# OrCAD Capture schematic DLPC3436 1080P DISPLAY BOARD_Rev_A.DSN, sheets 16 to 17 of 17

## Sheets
16 P07: FPGA - DAC Interface: size D
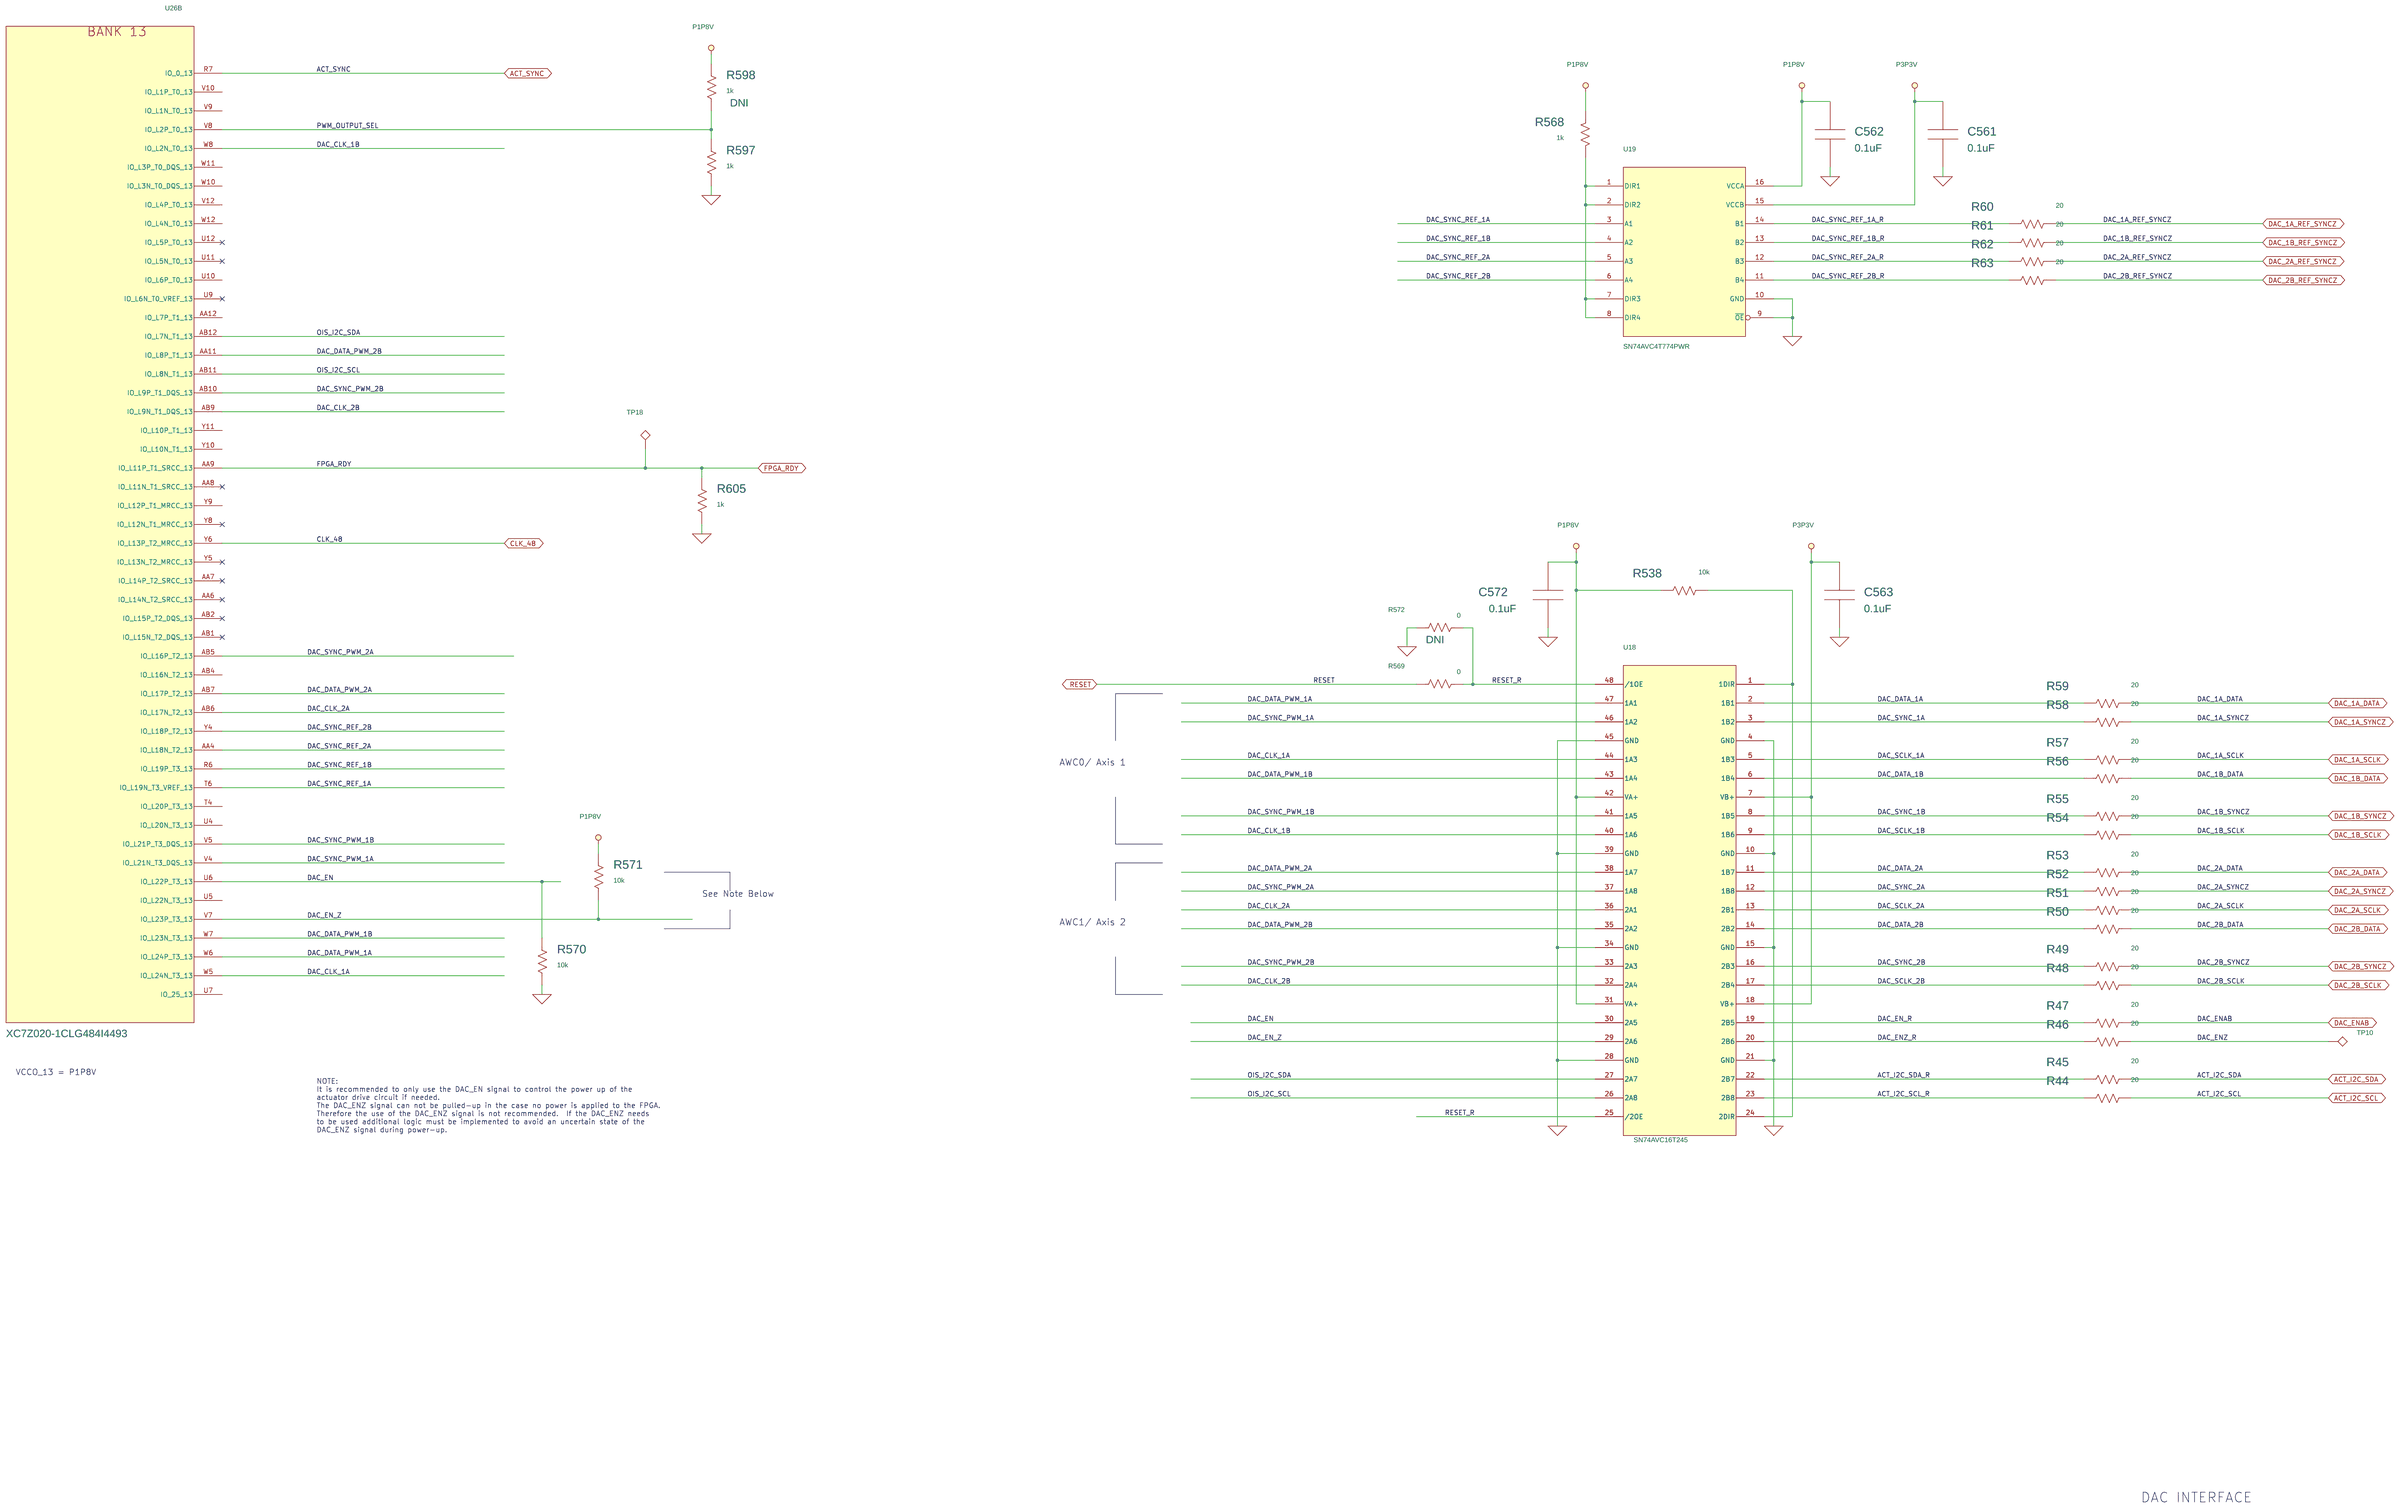
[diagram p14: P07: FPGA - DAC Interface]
17 P02: FPGA Boot, Flash, Reset: size D
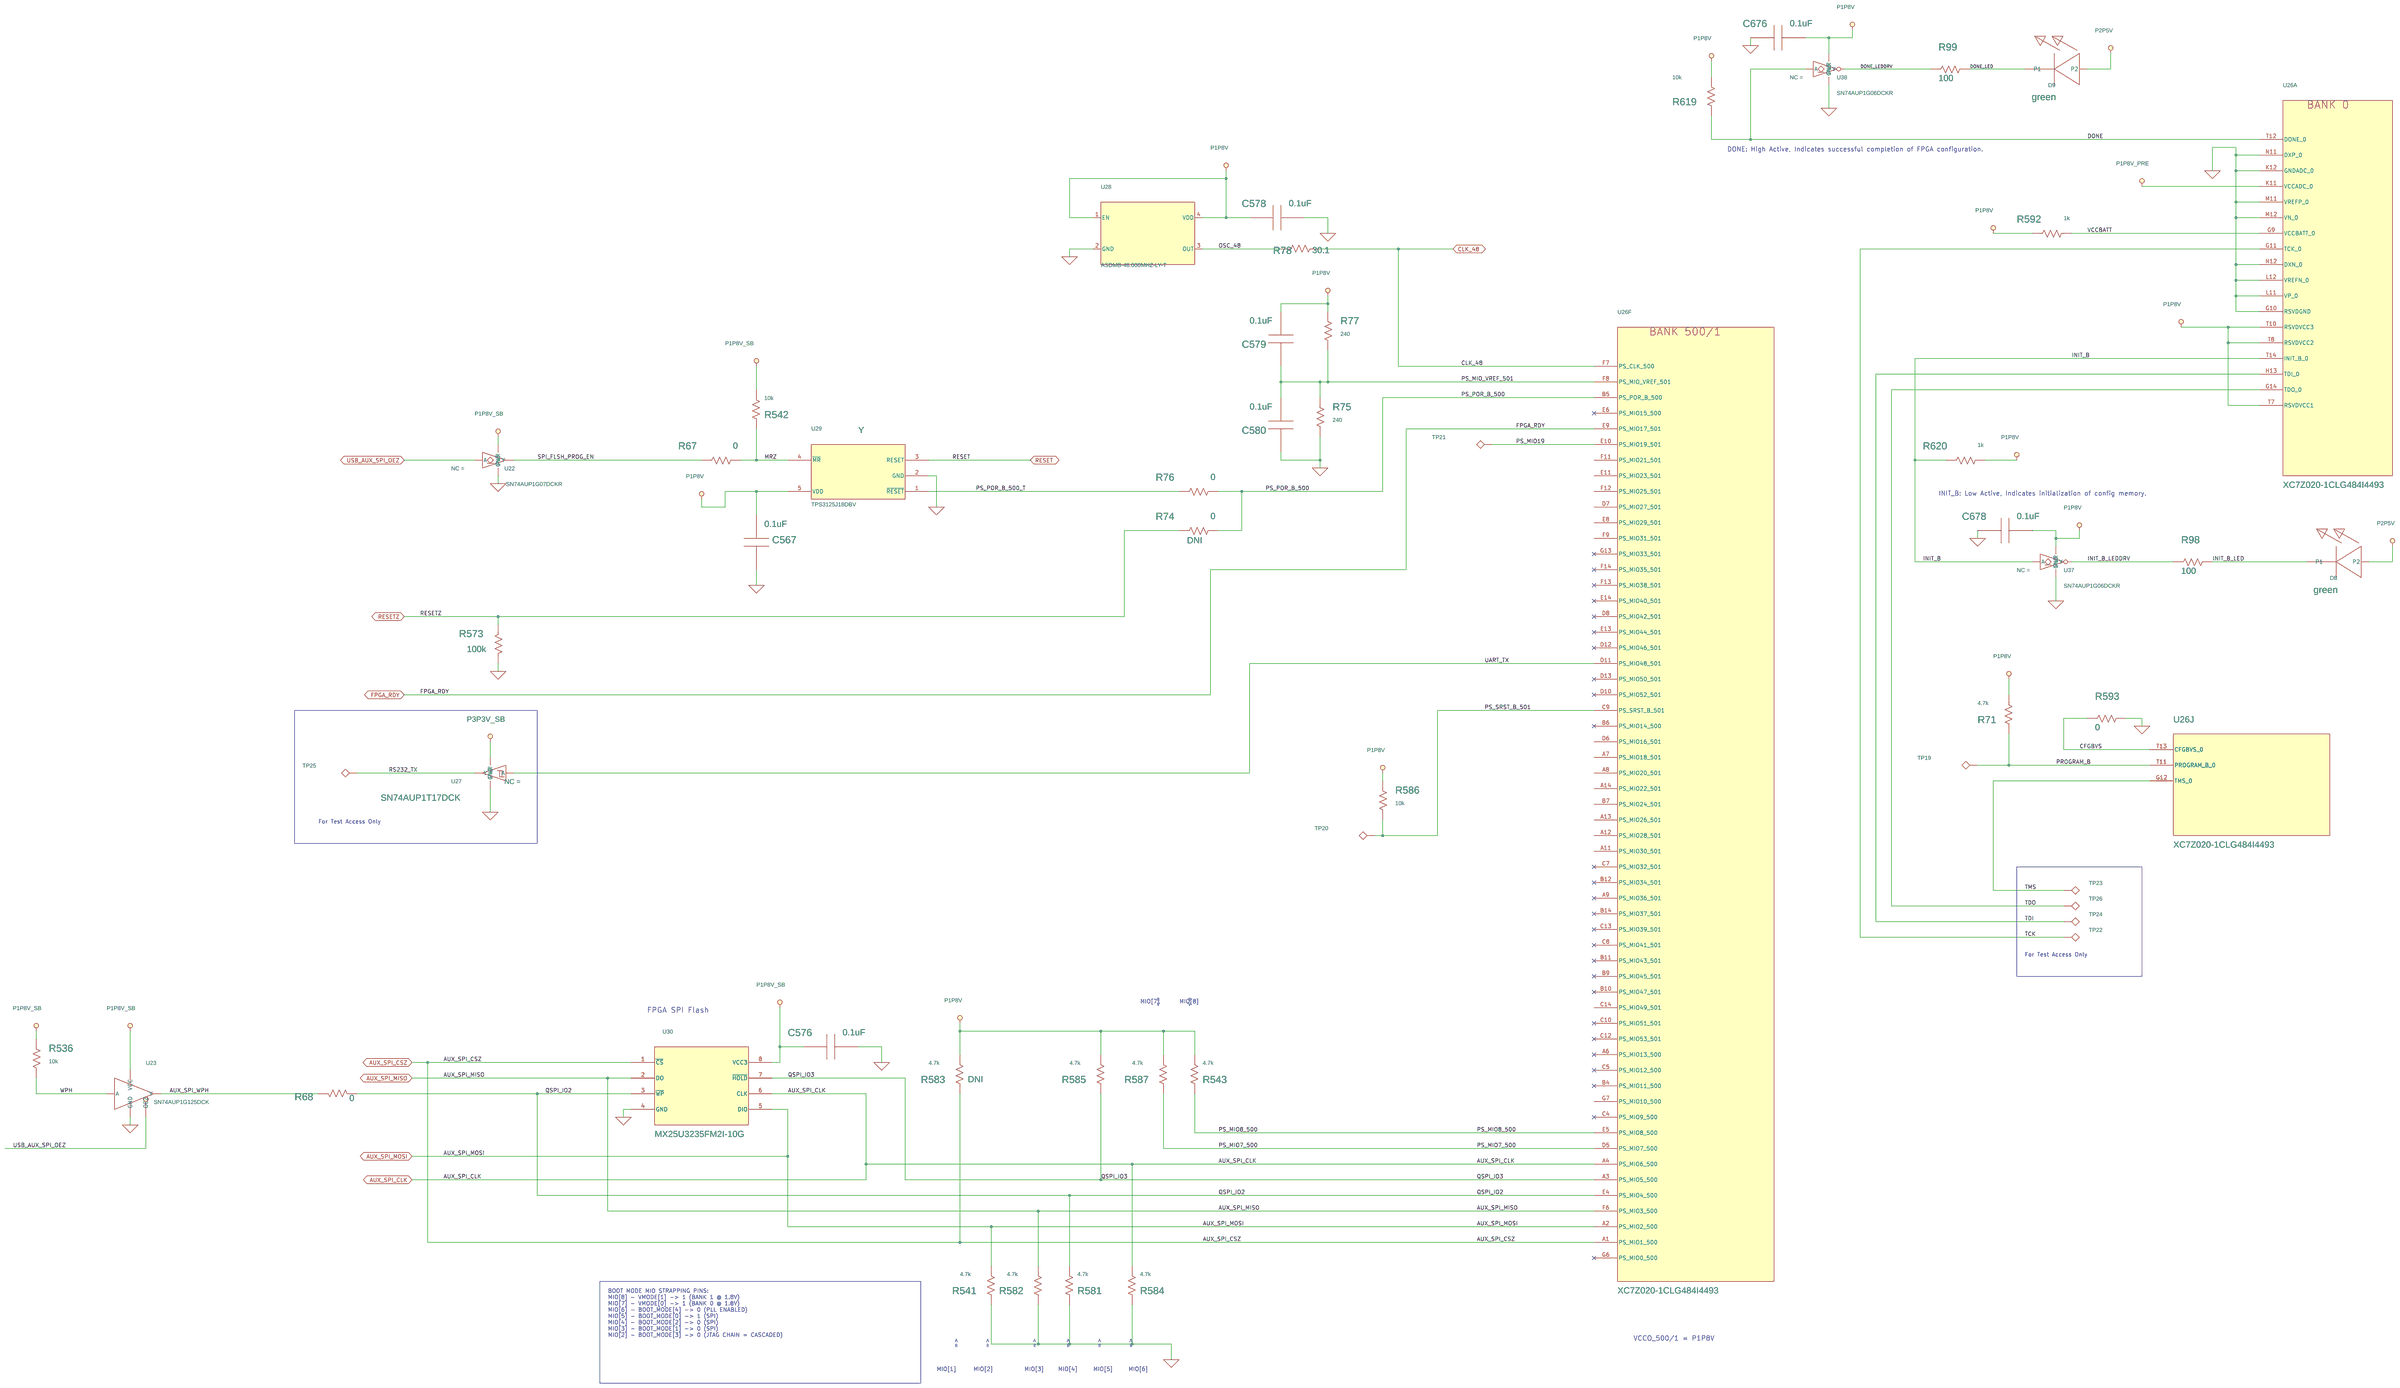
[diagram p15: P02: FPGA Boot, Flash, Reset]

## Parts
sheet P02: FPGA Boot, Flash, Reset
C567  0.1uF  [0402_AVXA]
C576  0.1uF  [0402_AVXA]
C578  0.1uF  [0402_AVXA]
C579  0.1uF  [0402_AVXA]
C580  0.1uF  [0402_AVXA]
C676  0.1uF  [0402_AVXA]
C678  0.1uF  [0402_AVXA]
D8  green  [1206]
D9  green  [1206]
R67  0  [0402]
R68  0  [0402]
R71  4.7k  [0402]
R74  0  [0402]
R75  240  [0402]
R76  0  [0402]
R77  240  [0402]
R78  30.1  [0402]
R98  100  [0402]
R99  100  [0402]
R536  10k  [0402]
R541  4.7k  [0402]
R542  10k  [0402]
R543  4.7k  [0402]
R573  100k  [0402]
R581  4.7k  [0402]
R582  4.7k  [0402]
R583  4.7k  [0402]
R584  4.7k  [0402]
R585  4.7k  [0402]
R586  10k  [0402]
R587  4.7k  [0402]
R592  1k  [0402]
R593  0  [0402]
R619  10k  [0402]
R620  1k  [0402]
TP19  TP,12mil Drill,32mil Pad  [HOLE_PLATED_12mil_DRILL_32mil_PAD]
TP20  TP,12mil Drill,32mil Pad  [HOLE_PLATED_12mil_DRILL_32mil_PAD]
TP21  TP,12mil Drill,32mil Pad  [HOLE_PLATED_12mil_DRILL_32mil_PAD]
TP22  TP40  [TP40]
TP23  TP40  [TP40]
TP24  TP40  [TP40]
TP25  TP40  [TP40]
TP26  TP40  [TP40]
U22  SN74AUP1G07DCK  [U_5_DCK]
U23  SN74AUP1G125DCK  [U_5_DCK]
U27  SN74AUP1T17DCK  [U_5_DCK]
U28  48MHz  [ECS-2018_2p5mmx2mm]
U29  TPS3125J18DBV  [DBV_R-PDS0-G5]
U30  MX25U3235FM2I-10G  [SOIC-8_208mil]
U37  SN74AUP1G06DCK  [U_5_DCK]
U38  SN74AUP1G06DCK  [U_5_DCK]
sheet P03: Parallel Video Input
U26  XC7Z020-1CLG484I4493  [Xilinx_CLG484]  (sections A,B,C,D,E,F,G,H,I,J)
sheet P07: FPGA - DAC Interface
C561  0.1uF  [0402_AVXA]
C562  0.1uF  [0402_AVXA]
C563  0.1uF  [0402_AVXA]
C572  0.1uF  [0402_AVXA]
R44  20  [0201_R]
R45  20  [0201_R]
R46  20  [0201_R]
R47  20  [0201_R]
R48  20  [0201_R]
R49  20  [0201_R]
R50  20  [0201_R]
R51  20  [0201_R]
R52  20  [0201_R]
R53  20  [0201_R]
R54  20  [0201_R]
R55  20  [0201_R]
R56  20  [0201_R]
R57  20  [0201_R]
R58  20  [0201_R]
R59  20  [0201_R]
R60  20  [0201_R]
R61  20  [0201_R]
R62  20  [0201_R]
R63  20  [0201_R]
R538  10k  [0402]
R568  1k  [0402]
R569  0  [0402]
R570  10k  [0402]
R571  10k  [0402]
R572  0  [0402]
R597  1k  [0402]
R598  1k  [0402]
R605  1k  [0402]
TP10  TP,12mil Drill,32mil Pad  [HOLE_PLATED_12mil_DRILL_32mil_PAD]
TP18  TP40  [TP40]
U18  SN74AVC16T245  [SOIC48-DGG_TI]
U19  SN74AVC4T774PWR  [TSSOP16_PW]

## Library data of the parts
C567 = PAS,CAP,NP,large: DigiKey: 445-4952-1-ND; DigiReel: 445-4952-6-ND; Family: passive; Index PN: 681; Install: Y; Lead Style: SMT; MFG: TDK; Material: x7r; P/D_NUM: C1005X7R1C104K050BC; Part Number: C1005X7R1C104K050BC; Part Specific: CAP CER .1UF 16V X7R 0402; TOLERANCE: 10%; Type: capacitor; VENDOR: TDK; VPC: 16V
C561-C563 C572 C576 C578-C580 C676 C678 = PAS,CAP,NP,large: DigiKey: 445-4952-1-ND; DigiReel: 445-4952-6-ND; Family: passive; Index PN: 681; Lead Style: SMT; MFG: TDK; Material: x7r; P/D_NUM: C1005X7R1C104K050BC; Part Number: C1005X7R1C104K050BC; Part Specific: CAP CER .1UF 16V X7R 0402; TOLERANCE: 10%; Type: capacitor; VENDOR: TDK; VPC: 16V
D8 D9 = PAS,DIODE,LED,large: DigiKey: 67-1357-1-ND; DigiReel: 67-1357-6-ND; Family: passive; Index PN: 31; Install: Y; Lead Style: SMT; MFG: Lumex; P/D_NUM: SML-LX1206GC-TR; Part Number: SML-LX1206GC-TR; Part Specific: LED 565NM WTR CLR GREEN 1206 SMD; Type: diode,led; VENDOR: Lumex
R67 R68 R76 = PAS,R,large: DigiKey: P0.0JCT-ND; DigiReel: P0.0JDKR-ND; Family: passive; Index PN: 687; Install: Y; Lead Style: SMT; MFG: Panasonic; Material: chip; P/D_NUM: ERJ-2GE0R00X; Part Number: ERJ-2GE0R00X; Part Specific: RES 0.0 OHM 1/16W 0402 SMD; Power: 1/16W; Type: resistor; VPC: 1/16W; Vendor: Panasonic
R71 R543 R581 R582 R584 R587 = PAS,R,large: DigiKey: P4.70KLCT-ND; DigiReel: P4.70KLDKR-ND; Family: passive; Index PN: 1219; Lead Style: SMT; MFG: Panasonic; P/D_NUM: ERJ-2RKF4701X; Part Number: ERJ-2RKF4701X; Part Specific: RES 4.7K OHM 1/10W 1% 0402 SMD; Type: resistor; VENDOR: Panasonic; VPC: 1/16W
R74 R572 = PAS,R,large: DigiKey: P0.0JCT-ND; DigiReel: P0.0JDKR-ND; Family: passive; Index PN: 687; Install: DNI; Lead Style: SMT; MFG: Panasonic; Material: chip; P/D_NUM: ERJ-2GE0R00X; Part Number: ERJ-2GE0R00X; Part Specific: RES 0.0 OHM 1/16W 0402 SMD; Power: 1/16W; Type: resistor; VPC: 1/16W; Vendor: Panasonic
R75 R77 = PAS,R,large: DigiKey: P240LCT-ND; DigiReel: P240LDKR-ND; Family: passive; Index PN: 1303; Lead Style: SMT; MFG: Panasonic; P/D_NUM: ERJ-2RKF2400X; Part Number: ERJ-2RKF2400X; Part Specific: RES SMD 240 OHM 1% 1/10W 0402; Type: resistor; VENDOR: Panasonic; VPC: 1/16W
R78 = PAS,R,large: DigiKey: P30.1LCT-ND; DigiReel: P30.1LDKR-ND; Family: passive; Index PN: 976; Lead Style: SMT; MFG: Panasonic; Material: chip; P/D_NUM: ERJ-2RKF30R1X; Part Number: ERJ-2RKF30R1X; Part Specific: RES 30.1 OHM 1/16W 1% 0402 SMD; Power: 1/16W; TOLERANCE: 1%; Type: resistor; VENDOR: Panasonic; VPC: 1/16W
R98 R99 = PAS,R,large: DigiKey: P100LCT-ND; DigiReel: P100LDKR-ND; Family: passive; Index PN: 690; Lead Style: SMT; MFG: Panasonic; Material: chip; P/D_NUM: ERJ-2RKF1000X; Part Number: ERJ-2RKF1000X; Part Specific: RES 100 OHM 1/10W 1% 0402 SMD; Power: 1/16W; TOLERANCE: 1%; Type: resistor; VENDOR: Panasonic; VPC: 1/16W
R536 R542 R586 R619 = PAS,R,large: DigiKey: P10.0KLCT-ND; DigiReel: P10.0KLDKR-ND; Family: passive; Index PN: 680; Install: Y; Lead Style: SMT; MFG: Panasonic; Material: chip; P/D_NUM: ERJ-2RKF1002X; Part Number: ERJ-2RKF1002X; Part Specific: RES SMD 10K OHM 1% 1/10W 0402; Power: 1/16W; TOLERANCE: 1%; Type: resistor; VENDOR: Panasonic; VPC: 1/16W
R541 R585 = PAS,R,large: DigiKey: P4.70KLCT-ND; DigiReel: P4.70KLDKR-ND; Family: passive; Index PN: 1219; Install: Y; Lead Style: SMT; MFG: Panasonic; P/D_NUM: ERJ-2RKF4701X; Part Number: ERJ-2RKF4701X; Part Specific: RES 4.7K OHM 1/10W 1% 0402 SMD; Type: resistor; VENDOR: Panasonic; VPC: 1/16W
R573 = PAS,R,large: DigiKey: 541-100KLCT-ND; DigiReel: 541-100KLDKR-ND; Family: passive; Index PN: 712; Lead Style: SMT; MFG: Vishay/Dale; Material: chip; P/D_NUM: CRCW0402100KFKED; Part Number: CRCW0402100KFKED; Part Specific: RES 100K OHM 1/10W 1% 0402 SMD; Power: 1/16W; TOLERANCE: 1%; Type: resistor; VPC: 1/16W; Vendor: Vishay/Dale
R583 = PAS,R,large: DigiKey: P4.70KLCT-ND; DigiReel: P4.70KLDKR-ND; Family: passive; Index PN: 1219; Install: DNI; Lead Style: SMT; MFG: Panasonic; P/D_NUM: ERJ-2RKF4701X; Part Number: ERJ-2RKF4701X; Part Specific: RES 4.7K OHM 1/10W 1% 0402 SMD; Type: resistor; VENDOR: Panasonic; VPC: 1/16W
R568 R592 R597 R605 R620 = PAS,R,large: DigiKey: P1.00KLCT-ND; DigiReel: P1.00KLDKR-ND; Family: passive; Index PN: 684; Install: Y; Lead Style: SMT; MFG: Panasonic; Material: chip; P/D_NUM: ERJ-2RKF1001X; Part Number: ERJ-2RKF1001X; Part Specific: RES 1.00K OHM 1/10W 1% 0402 SMD; Power: 1/16W; TOLERANCE: 1%; Type: resistor; VENDOR: Panasonic; VPC: 1/16W
R593 = PAS,R,large: DigiKey: P0.0JCT-ND; DigiReel: P0.0JDKR-ND; Family: passive; Index PN: 687; Lead Style: SMT; MFG: Panasonic; Material: chip; P/D_NUM: ERJ-2GE0R00X; Part Number: ERJ-2GE0R00X; Part Specific: RES 0.0 OHM 1/16W 0402 SMD; Power: 1/16W; Type: resistor; VENDOR: Panasonic; VPC: 1/16W
TP10 TP19-TP21 = EM,TERM,TESTPOINT: Family: board feature; Index PN: 122; Install: DNI; MFG: -- NOT A PART --; Type: hole,plated; Vendor: -- NOT A PART --
TP18 TP22-TP26 = EM,TERM,TESTPOINT: DigiKey: ---; DigiReel: ---; Family: board feature; Index PN: 995; Install: DNI; MFG: -- NOT A PART --; Type: hole,plated; Vendor: -- NOT A PART --
U22 = LOG,BUF,OPENDRN,SN74AUP1G07DCK: DigiKey: 296-18256-1-ND; DigiReel: 296-18256-6-ND; Family: logic; Index PN: 1027; Lead Style: SMT; MFG: Texas Instruments; P/D_NUM: SN74AUP1G07DCKR; Part Number: SN74AUP1G07DCKR; Part Specific: IC BUFF/DVR LOW PWR N-INV SC705, open drain; Type: buffer
U23 = LOG,BUF,SN74AUP1G125DCK: DigiKey: 296-21012-1-ND; DigiReel: 296-21012-6-ND; Family: logic; Lead Style: SMT; MFG: Texas Instruments; P/D_NUM: SN74AUP1G125DCKR; Part Number: SN74AUP1G125DCKR; Part Specific: IC BUS BUFFER TRI-ST SC70-5; Pin Cnt: 5; Type: buffer
U27 = LOG,BUF,SCHMITT,SN74AUP1T17DCK: DigiKey: 296-27395-1-ND; DigiReel: 296-27395-6-ND; Family: logic; Index PN: 1199; Lead Style: SMT; MFG: Texas Instruments; P/D_NUM: SN74AUP1T17DCKR; Part Number: SN74AUP1T17DCKR; Part Specific: IC BUFFER SCHMITT TRIG LP SC70-5; Type: buffer
U28 = ANA,OSC,4P,2X: DigiKey: 535-11198-1-ND; DigiReel: 535-11198-6-ND; Family: analog; Index PN: 1346; Install: Y; Lead Style: SMT; MFG: Abracon; P/D_NUM: ASDMB-48.000MHZ-LY-T; Part Number: ASDMB-48.000MHZ-LY-T; Part Specific: OSC MEMS 48.000MHZ CMOS SMD; Type: oscillator; VPC: 1.8V-3.3V; Vendor: Abracon
U29 = PWR,MON,TPS3125: DigiKey: 296-10898-1-ND; DigiReel: 296-10898-6-ND; Family: power; Index PN: 1160; Install: Y; Lead Style: SMT; MFG: Texas Instruments; Part Specific: IC 1.62V SUPPLY MONITOR SOT23-5; Type: monitor; Vendor: Texas Instruments
U30 = MEM,FLASH,SERIAL,W25XxxALxNIG: DigiKey: 1092-1137-ND; DigiReel: ---; Family: memory; Install: Y; Lead Style: SMT; MFG: Macronix; Part Specific: IC FLASH 32M SPI 104MHZ 8SOIC; Type: flash, spi; VENDOR: Macronix; VPC: 1.65-2.0V
U37 U38 = LOG,INV,OPENDRN,SN74AUP1G06DCK: DigiKey: 296-17562-1-ND; DigiReel: 296-17562-6-ND; Family: logic; Index PN: 1026; Lead Style: SMT; MFG: Texas Instruments; P/D_NUM: SN74AUP1G06DCKR; Part Number: SN74AUP1G06DCKR; Part Specific: IC INVERTER SINGLE 1INPUT SC705, open drain; Type: buffer
U26 = TIDLP,XPR_FPGA,Zynq-7020new_0: DigiKey: ---; DigiReel: ---; Family: processor; Index PN: 1304; Lead Style: SMT; MFG: Xilinx; Type: dlp; Vendor: Xilinx
R44-R63 = PAS,R,large: DigiKey: YAG2500CT-ND; DigiReel: YAG2500DKR-ND; Family: passive; Install: Y; Lead Style: SMT; MFG: Yageo; P/D_NUM: RC0201FR-0720RL; Part Number: RC0201FR-0720RL; Part Specific: RES SMD 20 OHM 1% 1/20W 0201; Power: 1%; Type: resistor; VENDOR: Yageo; VPC: 1/20W
R538 R570 R571 = PAS,R,large: DigiKey: P10.0KLCT-ND; DigiReel: P10.0KLDKR-ND; Family: passive; Index PN: 680; Lead Style: SMT; MFG: Panasonic; Material: chip; P/D_NUM: ERJ-2RKF1002X; Part Number: ERJ-2RKF1002X; Part Specific: RES SMD 10K OHM 1% 1/10W 0402; Power: 1/16W; TOLERANCE: 1%; Type: resistor; VENDOR: Panasonic; VPC: 1/16W
R569 = PAS,R,large: DigiKey: P0.0JCT-ND; DigiReel: P0.0JDKR-ND; Family: passive; Index PN: 687; Lead Style: SMT; MFG: Panasonic; Material: chip; P/D_NUM: ERJ-2GE0R00X; Part Number: ERJ-2GE0R00X; Part Specific: RES 0.0 OHM 1/16W 0402 SMD; Power: 1/16W; Type: resistor; VPC: 1/16W; Vendor: Panasonic
R598 = PAS,R,large: DigiKey: P1.00KLCT-ND; DigiReel: P1.00KLDKR-ND; Family: passive; Index PN: 684; Install: DNI; Lead Style: SMT; MFG: Panasonic; Material: chip; P/D_NUM: ERJ-2RKF1001X; Part Number: ERJ-2RKF1001X; Part Specific: RES 1.00K OHM 1/10W 1% 0402 SMD; Power: 1/16W; TOLERANCE: 1%; Type: resistor; VENDOR: Panasonic; VPC: 1/16W
U18 = SN74AVC16T245: DigiKey: 296-18197-1-ND; DigiKey Part Number: 296-18197-1-ND; DigiReel: 296-18197-6-ND; Install: Y; Lead Style: SMT; MFG: Texas Instruments; P/D_NUM: SN74AVC16T245DGGR; PART NUMBER: SN74AVC16T245DGGR; Part Specific: IC BUS TRANSCVR 16BIT DL 48TSSOP; Pin Cnt: 48; Type: transceiver; Vendor: Texas Instruments
U19 = LOG,XCVR,74x4T774: DigiKey: 296-24739-1-ND; DigiReel: 296-24739-6-ND; Family: logic; Index PN: 871; Lead Style: SMT; MFG: Texas Instruments; Part Specific: IC BUS TRANSCVR 4BIT DL 16TSSOP; Pin Cnt: 16; Type: transceiver; Vendor: Texas Instruments

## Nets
DGND: C561.2(N) C562.2(N) C563.2(N) C567.1(P) C572.2(N) C576.2(N) C578.2(N) C580.2(N) C676.1(P) C678.1(P) R75.2(N2) R541.1(N1) R570.2(N2) R572.1(N1) R573.1(N1) R581.1(N1) R582.1(N1) R584.1(N1) R593.1(N1) R597.2(N2) R605.2(N2) U18.4(GND) U18.10(GND) U18.15(GND) U18.21(GND) U18.28(GND) U18.34(GND) U18.39(GND) U18.45(GND) U19.9(~{OE}) U19.10(GND) U22.3(GND) U23.3(GND) U26.G10(RSVDGND) U26.K12(GNDADC_0) U26.L11(VP_0) U26.L12(VREFN_0) U26.M11(VREFP_0) U26.M12(VN_0) U26.N11(DXP_0) U26.N12(DXN_0) U27.3(GND) U28.2(GND) U29.2(GND) U30.4(GND) U37.3(GND) U38.3(GND) ; also on sheet 1 2 4 7 8 9 10 11 12 13 14 15
VCCBATT: R592.1(N1) U26.G9(VCCBATT_0)
ACT_I2C_SCL: R44.1(N1) ; also on sheet 10
ACT_I2C_SCL_R: R44.2(N2) U18.23(2B8)
ACT_I2C_SDA: R45.1(N1) ; also on sheet 10
ACT_I2C_SDA_R: R45.2(N2) U18.22(2B7)
ACT_SYNC: U26.R7(IO_0_13) ; also on sheet 4
AUX_SPI_CLK: R584.2(N2) U26.A4(PS_MIO6_500) U30.6(CLK) ; also on sheet 9
AUX_SPI_CSZ: R583.1(N1) U26.A1(PS_MIO1_500) U30.1(~{CS}) ; also on sheet 9
AUX_SPI_MISO: R582.2(N2) U26.F6(PS_MIO3_500) U30.2(DO) ; also on sheet 9
AUX_SPI_MOSI: R541.2(N2) U26.A2(PS_MIO2_500) U30.5(DIO) ; also on sheet 9
AUX_SPI_WPH: R68.2(N2) U23.4(Y)
CFGBVS: R593.2(N2) U26.T13(CFGBVS_0)
CLK_48: R78.2(N2) U26.F7(PS_CLK_500) U26.Y6(IO_L13P_T2_MRCC_13)
DAC_1A_DATA: R59.1(N1) ; also on sheet 10
DAC_1A_REF_SYNCZ: R60.1(N1) ; also on sheet 10
DAC_1A_SCLK: R57.1(N1) ; also on sheet 10
DAC_1A_SYNCZ: R58.1(N1) ; also on sheet 10
DAC_1B_DATA: R56.1(N1) ; also on sheet 10
DAC_1B_REF_SYNCZ: R61.1(N1) ; also on sheet 10
DAC_1B_SCLK: R54.1(N1) ; also on sheet 10
DAC_1B_SYNCZ: R55.1(N1) ; also on sheet 10
DAC_2A_DATA: R53.1(N1) ; also on sheet 10
DAC_2A_REF_SYNCZ: R62.1(N1) ; also on sheet 10
DAC_2A_SCLK: R51.1(N1) ; also on sheet 10
DAC_2A_SYNCZ: R52.1(N1) ; also on sheet 10
DAC_2B_DATA: R50.1(N1) ; also on sheet 10
DAC_2B_REF_SYNCZ: R63.1(N1) ; also on sheet 10
DAC_2B_SCLK: R48.1(N1) ; also on sheet 10
DAC_2B_SYNCZ: R49.1(N1) ; also on sheet 10
DAC_CLK_1A: U18.44(1A3) U26.W5(IO_L24N_T3_13)
DAC_CLK_1B: U18.40(1A6) U26.W8(IO_L2N_T0_13)
DAC_CLK_2A: U18.36(2A1) U26.AB6(IO_L17N_T2_13)
DAC_CLK_2B: U18.32(2A4) U26.AB9(IO_L9N_T1_DQS_13)
DAC_DATA_1A: R59.2(N2) U18.2(1B1)
DAC_DATA_1B: R56.2(N2) U18.6(1B4)
DAC_DATA_2A: R53.2(N2) U18.11(1B7)
DAC_DATA_2B: R50.2(N2) U18.14(2B2)
DAC_DATA_PWM_1A: U18.47(1A1) U26.W6(IO_L24P_T3_13)
DAC_DATA_PWM_1B: U18.43(1A4) U26.W7(IO_L23N_T3_13)
DAC_DATA_PWM_2A: U18.38(1A7) U26.AB7(IO_L17P_T2_13)
DAC_DATA_PWM_2B: U18.35(2A2) U26.AA11(IO_L8P_T1_13)
DAC_EN: R570.1(N1) U18.30(2A5) U26.U6(IO_L22P_T3_13)
DAC_EN_R: R47.2(N2) U18.19(2B5)
DAC_EN_Z: R571.2(N2) U18.29(2A6) U26.V7(IO_L23P_T3_13)
DAC_ENAB: R47.1(N1) ; also on sheet 11
DAC_ENZ: R46.1(N1) TP10.1(P1)
DAC_ENZ_R: R46.2(N2) U18.20(2B6)
DAC_SCLK_1A: R57.2(N2) U18.5(1B3)
DAC_SCLK_1B: R54.2(N2) U18.9(1B6)
DAC_SCLK_2A: R51.2(N2) U18.13(2B1)
DAC_SCLK_2B: R48.2(N2) U18.17(2B4)
DAC_SYNC_1A: R58.2(N2) U18.3(1B2)
DAC_SYNC_1B: R55.2(N2) U18.8(1B5)
DAC_SYNC_2A: R52.2(N2) U18.12(1B8)
DAC_SYNC_2B: R49.2(N2) U18.16(2B3)
DAC_SYNC_PWM_1A: U18.46(1A2) U26.V4(IO_L21N_T3_DQS_13)
DAC_SYNC_PWM_1B: U18.41(1A5) U26.V5(IO_L21P_T3_DQS_13)
DAC_SYNC_PWM_2A: U18.37(1A8) U26.AB5(IO_L16P_T2_13)
DAC_SYNC_PWM_2B: U18.33(2A3) U26.AB10(IO_L9P_T1_DQS_13)
DAC_SYNC_REF_1A: U19.3(A1) U26.T6(IO_L19N_T3_VREF_13)
DAC_SYNC_REF_1A_R: R60.2(N2) U19.14(B1)
DAC_SYNC_REF_1B: U19.4(A2) U26.R6(IO_L19P_T3_13)
DAC_SYNC_REF_1B_R: R61.2(N2) U19.13(B2)
DAC_SYNC_REF_2A: U19.5(A3) U26.AA4(IO_L18N_T2_13)
DAC_SYNC_REF_2A_R: R62.2(N2) U19.12(B3)
DAC_SYNC_REF_2B: U19.6(A4) U26.Y4(IO_L18P_T2_13)
DAC_SYNC_REF_2B_R: R63.2(N2) U19.11(B4)
DONE: R619.1(N1) U26.T12(DONE_0) U38.2(A)
DONE_LED: D9.1(P1) R99.1(N1)
DONE_LEDDRV: R99.2(N2) U38.4(Y)
FPGA_RDY: R605.1(N1) TP18.1(P1) U26.AA9(IO_L11P_T1_SRCC_13) U26.E9(PS_MIO17_501) ; also on sheet 4
INIT_B: R620.2(N2) U26.T14(INIT_B_0) U37.2(A)
INIT_B_LED: D8.1(P1) R98.1(N1)
INIT_B_LEDDRV: R98.2(N2) U37.4(Y)
MRZ: R67.1(N1) R542.1(N1) U29.4(~{MR})
OIS_I2C_SCL: U18.26(2A8) U26.AB11(IO_L8N_T1_13)
OIS_I2C_SDA: U18.27(2A7) U26.AB12(IO_L7N_T1_13)
OSC_48: R78.1(N1) U28.3(OUT)
P1P8V: C562.1(P) C567.2(N) C572.1(P) C578.1(P) C579.1(P) C676.2(N) C678.2(N) R71.2(N2) R77.1(N1) R538.2(N2) R543.2(N2) R568.1(N1) R571.1(N1) R583.2(N2) R585.2(N2) R586.1(N1) R587.2(N2) R592.2(N2) R598.1(N1) R619.2(N2) R620.1(N1) U18.31(VA+) U18.42(VA+) U19.16(VCCA) U26.T7(RSVDVCC1) U26.T8(RSVDVCC2) U26.T10(RSVDVCC3) U28.1(EN) U28.4(VDD) U29.5(VDD) U37.5(PWR) U38.5(PWR) ; also on sheet 2 13
P1P8V_PRE: U26.K11(VCCADC_0) ; also on sheet 2
P1P8V_SB: C576.1(P) R536.1(N1) R542.2(N2) U22.5(PWR) U23.5(VCC) U30.8(VCC3) ; also on sheet 9
P2P5V: D8.2(P2) D9.2(P2) ; also on sheet 2
P3P3V: C561.1(P) C563.1(P) U18.7(VB+) U18.18(VB+) U19.15(VCCB) ; also on sheet 2 10 11
P3P3V_SB: U27.5(PWR) ; also on sheet 2 7 9 15
PROGRAM_B: R71.1(N1) TP19.1(P1) U26.T11(PROGRAM_B_0)
PS_MIO7_500: R587.1(N1) U26.D5(PS_MIO7_500)
PS_MIO8_500: R543.1(N1) U26.E5(PS_MIO8_500)
PS_MIO19: TP21.1(P1) U26.E10(PS_MIO19_501)
PS_MIO_VREF_501: C579.2(N) C580.1(P) R75.1(N1) R77.2(N2) U26.F8(PS_MIO_VREF_501)
PS_POR_B_500: R74.1(N1) R76.1(N1) U26.B5(PS_POR_B_500)
PS_POR_B_500_T: R76.2(N2) U29.1(~{RESET})
PS_SRST_B_501: R586.2(N2) TP20.1(P1) U26.C9(PS_SRST_B_501)
PWM_OUTPUT_SEL: R597.1(N1) R598.2(N2) U26.V8(IO_L2P_T0_13)
QSPI_IO2: R68.1(N1) R581.2(N2) U26.E4(PS_MIO4_500) U30.3(~{WP})
QSPI_IO3: R585.1(N1) U26.A3(PS_MIO5_500) U30.7(~{HOLD})
RESET: R569.1(N1) U29.3(RESET)
RESET_R: R569.2(N2) R572.2(N2) U18.25(/2OE) U18.48(/1OE)
RESETZ: R74.2(N2) R573.2(N2) ; also on sheet 8 9 15
RS232_TX: TP25.1(P1) U27.4(Y)
SPI_FLSH_PROG_EN: R67.2(N2) U22.4(Y)
TCK: TP22.1(P1) U26.G11(TCK_0)
TDI: TP24.1(P1) U26.H13(TDI_0)
TDO: TP26.1(P1) U26.G14(TDO_0)
TMS: TP23.1(P1) U26.G12(TMS_0)
UART_TX: U26.D11(PS_MIO48_501) U27.2(A)
USB_AUX_SPI_OEZ: U22.2(A) U23.1(OEZ) ; also on sheet 9
WPH: R536.2(N2) U23.2(A)
N23454579: R538.1(N1) U18.1(1DIR) U18.24(2DIR)
N23455312: R568.2(N2) U19.1(DIR1) U19.2(DIR2) U19.7(DIR3) U19.8(DIR4)

Not connected (* = marked no-connect by the designer): U26 A6(PS_MIO13_500)* A7(PS_MIO18_501) A8(PS_MIO20_501) A9(PS_MIO36_501)* A11(PS_MIO30_501) A12(PS_MIO28_501) A13(PS_MIO26_501) A14(PS_MIO22_501) AA6(IO_L14N_T2_SRCC_13)* AA7(IO_L14P_T2_SRCC_13)* AA8(IO_L11N_T1_SRCC_13)* AA12(IO_L7P_T1_13) AB1(IO_L15N_T2_DQS_13)* AB2(IO_L15P_T2_DQS_13)* AB4(IO_L16N_T2_13) B4(PS_MIO11_500)* B6(PS_MIO14_500)* B7(PS_MIO24_501) B9(PS_MIO45_501)* B10(PS_MIO47_501)* B11(PS_MIO43_501)* B12(PS_MIO34_501)* B14(PS_MIO37_501)* C4(PS_MIO9_500)* C5(PS_MIO12_500)* C7(PS_MIO32_501)* C8(PS_MIO41_501)* C10(PS_MIO51_501)* C12(PS_MIO53_501)* C13(PS_MIO39_501)* C14(PS_MIO49_501) D6(PS_MIO16_501) D7(PS_MIO27_501) D8(PS_MIO42_501)* D10(PS_MIO52_501)* D12(PS_MIO46_501)* D13(PS_MIO50_501)* E6(PS_MIO15_500)* E8(PS_MIO29_501) E11(PS_MIO23_501) E13(PS_MIO44_501)* E14(PS_MIO40_501)* F9(PS_MIO31_501) F11(PS_MIO21_501) F12(PS_MIO25_501) F13(PS_MIO38_501)* F14(PS_MIO35_501)* G6(PS_MIO0_500)* G7(PS_MIO10_500) G13(PS_MIO33_501)* T4(IO_L20P_T3_13) U4(IO_L20N_T3_13) U5(IO_L22N_T3_13) U7(IO_25_13) U9(IO_L6N_T0_VREF_13)* U10(IO_L6P_T0_13) U11(IO_L5N_T0_13)* U12(IO_L5P_T0_13)* V9(IO_L1N_T0_13) V10(IO_L1P_T0_13) V12(IO_L4P_T0_13) W10(IO_L3N_T0_DQS_13) W11(IO_L3P_T0_DQS_13) W12(IO_L4N_T0_13) Y5(IO_L13N_T2_MRCC_13)* Y8(IO_L12N_T1_MRCC_13)* Y9(IO_L12P_T1_MRCC_13) Y10(IO_L10N_T1_13) Y11(IO_L10P_T1_13)

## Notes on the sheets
sheet 16
- AWC0/ Axis 1
- See Note Below
- AWC1/ Axis 2
- VCCO_13 = P1P8V
- NOTE:
  It is recommended to only use the DAC_EN signal to control the power up of the
  actuator drive circuit if needed.
  The DAC_ENZ signal can not be pulled-up in the case no power is applied to the FPGA.
  Therefore the use of the DAC_ENZ signal is not recommended.  If the DAC_ENZ needs
  to be used additional logic must be implemented to avoid an uncertain state of the
  DAC_ENZ signal during power-up.
- DAC INTERFACE
sheet 17
- DONE: High Active, Indicates successful completion of FPGA configuration.
- INIT_B: Low Active, Indicates initialization of config memory.
- For Test Access Only
- For Test Access Only
- FPGA SPI Flash
- MIO[7]
- <=
- MIO[8]
- <=
- BOOT MODE MIO STRAPPING PINS:
  MIO[8] - VMODE[1] -> 1 (BANK 1 @ 1.8V)
  MIO[7] - VMODE[0] -> 1 (BANK 0 @ 1.8V)
  MIO[6] - BOOT_MODE[4] -> 0 (PLL ENABLED)
  MIO[5] - BOOT_MODE[0] -> 1 (SPI)
  MIO[4] - BOOT_MODE[2] -> 0 (SPI)
  MIO[3] - BOOT_MODE[1] -> 0 (SPI)
  MIO[2] - BOOT_MODE[3] -> 0 (JTAG CHAIN = CASCADED)
- VCCO_500/1 = P1P8V
- =>
- =>
- =>
- =>
- =>
- =>
- MIO[1]
- MIO[2]
- MIO[3]
- MIO[4]
- MIO[5]
- MIO[6]
